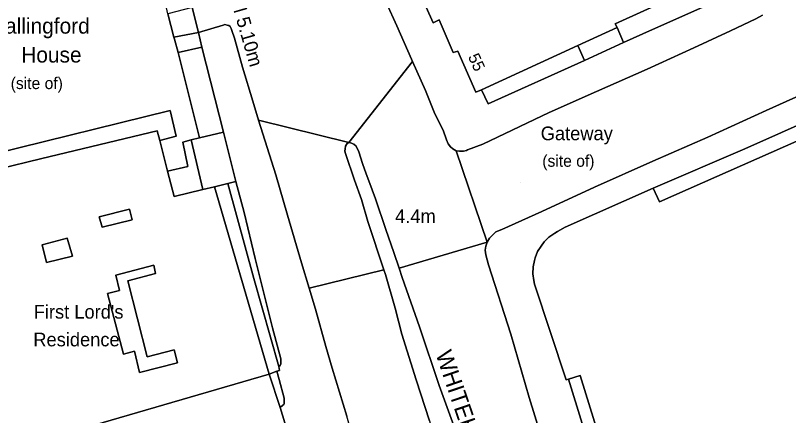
# Model space of a CAD drawing. Extents: x 529240 to 530363, y 179600 to 180767.
# Drawn here: x 530056.2 to 530155.2, y 180160.9 to 180212.1 of the extents above; entities that cross this region are included whole.
import ezdxf

# ---------------------------------------------------------------- set-up
doc = ezdxf.new("R2010")
doc.units = 0
for name, color, linetype in [('Building', 7, 'Continuous'), ('General surface', 7, 'Continuous'), ('Road Or Track', 7, 'Continuous'), ('Roadside', 7, 'Continuous'), ('Unclassified', 7, 'Continuous')]:
    doc.layers.add(name, color=color, linetype=linetype)

msp = doc.modelspace()

# ---------------------------------------------------------------- linework, layer by layer
at = {"layer": 'Building'}
for points in [[(530176.2, 180236.5), (530175.85, 180237.25), (530176.25, 180237.5), (530168, 180256.75), (530156.05, 180251.15), (530155.8, 180251.45), (530132.55, 180240.6), (530132.8, 180239.85), (530104.2, 180226.6), (530106.65, 180221.35), (530106.2, 180221.15), (530107.95, 180217.25), (530107.2, 180216.85), (530109.7, 180211.2), (530110.5, 180211.55), (530112.3, 180207.4), (530112.9, 180207.55), (530115.2, 180202.3), (530115.9, 180202.6)], [(530133.3, 180210.6), (530133.05, 180211.05), (530139.9, 180214.2), (530140.15, 180213.75), (530154.3, 180220.05)], [(530107.2, 180216.85), (530109.7, 180211.2), (530110.5, 180211.55), (530112.3, 180207.4), (530112.9, 180207.55), (530115.2, 180202.3), (530115.9, 180202.6), (530128.25, 180208.3), (530133.3, 180210.6), (530133.05, 180211.05), (530139.9, 180214.2)], [(530128.25, 180208.3), (530133.3, 180210.6)], [(530115.9, 180202.6), (530128.25, 180208.3)], [(530137.9, 180190), (530138.7, 180188.25), (530169.15, 180201.7), (530168.45, 180203.4)], [(530169.15, 180201.7), (530138.7, 180188.25), (530137.9, 180190), (530126.65, 180185), (530125.65, 180184.45), (530125.3, 180184.25), (530124.55, 180183.75), (530123.95, 180183.15), (530123.55, 180182.6), (530123.1, 180181.9), (530122.8, 180181.1), (530122.7, 180180.75), (530122.55, 180179.95), (530122.5, 180179.05), (530122.6, 180178.2), (530122.7, 180177.7), (530126.75, 180165.45), (530127.05, 180165.55), (530128.55, 180166), (530132.6, 180152.9)], [(530054.35, 180155.6), (530059.15, 180156.95), (530060.4, 180157.3), (530065.15, 180158.65), (530065.1, 180159.3), (530088.7, 180166.2), (530081.7, 180190.2), (530080.2, 180189.85), (530076.55, 180188.95), (530075.7, 180192.2), (530074.7, 180196.1), (530074.35, 180197.35), (530059.6, 180193.8), (530053.95, 180192.45)], [(530074.7, 180196.1), (530074.35, 180197.35), (530059.6, 180193.8), (530053.95, 180192.45)], [(530075.7, 180192.2), (530074.7, 180196.1)], [(530080.2, 180189.85), (530076.55, 180188.95), (530075.7, 180192.2)], [(530081.7, 180190.2), (530080.2, 180189.85)], [(530088.7, 180166.2), (530081.7, 180190.2)], [(530127.05, 180165.55), (530126.75, 180165.45), (530122.7, 180177.7), (530122.6, 180178.2), (530122.5, 180179.05), (530122.55, 180179.95), (530122.7, 180180.75), (530122.8, 180181.1), (530123.1, 180181.9), (530123.55, 180182.6), (530123.95, 180183.15), (530124.55, 180183.75), (530125.3, 180184.25), (530125.65, 180184.45), (530126.65, 180185), (530137.9, 180190)], [(530066.95, 180186.35), (530070.8, 180187.3), (530071.15, 180185.95), (530067.3, 180185), (530066.95, 180186.35)], [(530059.65, 180182.75), (530062.85, 180183.6), (530063.5, 180181.3), (530060.2, 180180.5), (530059.65, 180182.75)], [(530076.95, 180167.65), (530072.1, 180166.4), (530071.45, 180169.15), (530070.05, 180168.75), (530068, 180176.5), (530069.55, 180176.9), (530069.05, 180178.85), (530073.95, 180180.15), (530074.15, 180179.1), (530070.6, 180178.15), (530073.1, 180168.4), (530076.55, 180169.3), (530076.95, 180167.65)], [(530088.7, 180166.2), (530065.1, 180159.3), (530065.15, 180158.65), (530060.4, 180157.3)], [(530090.1, 180161.9), (530088.7, 180166.2)], [(530131.85, 180152.65), (530132.6, 180152.9), (530128.55, 180166), (530127.05, 180165.55)], [(530094.1, 180148.85), (530094.5, 180148.95), (530092.3, 180156.65), (530091.75, 180156.6), (530090.1, 180161.9)]]:
    msp.add_lwpolyline(points, dxfattribs=at)
for points in [[(530078.85, 180213.15), (530075.75, 180212.35), (530076.5, 180209.35), (530079.65, 180209.95)], [(530080.1, 180208.05), (530079.65, 180209.95), (530076.5, 180209.35), (530076.6, 180209.1), (530077.05, 180207.4)], [(530079.8, 180196.45), (530082.85, 180197.2), (530080.1, 180208.05), (530077.05, 180207.4)], [(530082.85, 180197.2), (530079.8, 180196.45), (530078.7, 180196.2), (530080.2, 180189.85), (530081.7, 180190.2), (530083.4, 180190.6), (530084.45, 180190.85)], [(530075.7, 180192.2), (530076.55, 180188.95), (530080.2, 180189.85), (530078.7, 180196.2), (530077.65, 180195.9), (530078.3, 180192.8)], [(530067.3, 180185), (530071.15, 180185.95), (530070.8, 180187.3), (530066.95, 180186.35)], [(530060.2, 180180.5), (530063.5, 180181.3), (530062.85, 180183.6), (530059.65, 180182.75)], [(530072.1, 180166.4), (530076.95, 180167.65), (530076.55, 180169.3), (530073.1, 180168.4), (530070.6, 180178.15), (530074.15, 180179.1), (530073.95, 180180.15), (530069.05, 180178.85), (530069.55, 180176.9), (530068, 180176.5), (530070.05, 180168.75), (530071.45, 180169.15)], [(530067.25, 180135.25), (530068.1, 180135.4), (530074.15, 180136.65), (530073.1, 180140.65), (530074, 180142.75), (530074.15, 180143.1), (530075.55, 180143.5), (530078.35, 180144.35), (530076.6, 180150.7), (530083.7, 180152.85), (530085.75, 180146.55), (530094.1, 180148.85), (530094.5, 180148.95), (530092.3, 180156.65), (530091.75, 180156.6), (530090.1, 180161.9), (530088.7, 180166.2), (530065.1, 180159.3), (530065.15, 180158.65), (530060.4, 180157.3), (530062.85, 180149.4), (530065.3, 180141.5)]]:
    msp.add_lwpolyline(points, close=True, dxfattribs=at)
at = {"layer": 'General surface'}
msp.add_lwpolyline([(530053.5, 180194.4), (530076.05, 180199.95), (530076.8, 180196.65), (530074.7, 180196.1), (530075.7, 180192.2), (530078.3, 180192.8), (530077.65, 180195.9), (530078.7, 180196.2), (530079.8, 180196.45), (530077.05, 180207.4), (530076.6, 180209.1), (530076.5, 180209.35), (530075.75, 180212.35), (530075.25, 180214.5), (530074, 180219.4), (530072.7, 180224.65), (530071.55, 180224.35), (530069.85, 180231.2), (530067.45, 180230.6), (530070.25, 180219.65), (530060.6, 180217.35), (530050.6, 180214.95)], dxfattribs=at)
for points in [[(530134.1, 180208.65), (530137.8, 180210.35), (530151.5, 180216.45), (530153.85, 180217.65), (530154.4, 180217.9), (530154.65, 180218.15), (530154.75, 180218.3), (530154.75, 180218.5), (530154.8, 180218.6), (530154.8, 180218.75), (530154.75, 180218.85), (530154.75, 180219.1), (530154.3, 180220.05), (530140.15, 180213.75), (530139.9, 180214.2), (530133.05, 180211.05), (530133.3, 180210.6)], [(530133.3, 180210.6), (530128.25, 180208.3), (530129.1, 180206.35), (530134.1, 180208.65)], [(530129.1, 180206.35), (530128.25, 180208.3), (530115.9, 180202.6), (530116.75, 180200.8)], [(530137.9, 180190), (530138.7, 180188.25), (530169.15, 180201.7), (530168.45, 180203.4), (530149.65, 180195.05)], [(530074.7, 180196.1), (530076.8, 180196.65), (530076.05, 180199.95), (530053.5, 180194.4), (530053.95, 180192.45), (530059.6, 180193.8), (530074.35, 180197.35)], [(530083.4, 180190.6), (530081.7, 180190.2), (530088.7, 180166.2), (530089.7, 180166.55), (530090.05, 180166.65), (530089.95, 180167.15), (530086.75, 180178.45)], [(530089.95, 180167.15), (530090.1, 180167.3), (530090.2, 180167.5), (530090.2, 180168.15), (530089.15, 180172.1), (530086.9, 180181), (530085.5, 180186.9), (530084.45, 180190.85), (530083.4, 180190.6), (530086.75, 180178.45)], [(530066.95, 180186.35), (530067.3, 180185), (530071.15, 180185.95), (530070.8, 180187.3)], [(530059.65, 180182.75), (530060.2, 180180.5), (530063.5, 180181.3), (530062.85, 180183.6)], [(530076.95, 180167.65), (530076.55, 180169.3), (530073.1, 180168.4), (530070.6, 180178.15), (530074.15, 180179.1), (530073.95, 180180.15), (530069.05, 180178.85), (530069.55, 180176.9), (530068, 180176.5), (530070.05, 180168.75), (530071.45, 180169.15), (530072.1, 180166.4)], [(530088.7, 180166.2), (530090.1, 180161.9), (530090.45, 180162.2), (530090.6, 180162.3), (530090.65, 180162.4), (530090.65, 180163.1), (530090, 180165.5), (530089.7, 180166.55)], [(530127.05, 180165.55), (530130.75, 180153.65), (530131.85, 180152.65), (530132.6, 180152.9), (530128.55, 180166)]]:
    msp.add_lwpolyline(points, close=True, dxfattribs=at)
at = {"layer": 'Road Or Track'}
for points in [[(530098.7, 180225.5), (530098.7, 180225), (530098.8, 180224.55), (530098.95, 180224.15), (530099.65, 180222.75), (530102.4, 180216.65), (530105.05, 180210.8), (530106.95, 180206.55), (530107.08, 180206.25)], [(530078.85, 180213.15), (530079.65, 180209.95), (530082.8, 180210.9), (530083.05, 180210.95), (530083.35, 180210.9), (530083.55, 180210.85), (530083.7, 180210.7), (530083.85, 180210.45), (530083.95, 180210.2), (530084.25, 180209.2), (530085.3, 180205.5), (530086.6, 180201.15), (530087.36, 180198.73), (530098.9, 180195.85), (530107.08, 180206.25), (530106.95, 180206.55), (530105.05, 180210.8), (530102.4, 180216.65)], [(530116.65, 180183.1), (530116.95, 180183.6), (530117.35, 180184.05), (530117.75, 180184.4), (530118.5, 180184.7), (530123.65, 180187), (530130.4, 180190.15), (530137.85, 180193.45), (530144.9, 180196.55), (530152.4, 180199.95), (530158.75, 180202.8), (530165.95, 180206.05), (530172.5, 180209.05), (530186.82, 180215.54)], [(530151.9, 180212.15), (530151.05, 180211.7), (530147.8, 180210.15), (530143.1, 180208), (530137.15, 180205.25), (530130.65, 180202.4), (530124.6, 180199.7), (530116.1, 180195.65), (530114.1, 180194.9), (530114, 180194.85), (530113.6, 180194.75), (530113.1, 180194.75), (530112.65, 180194.8), (530116.65, 180183.1), (530116.95, 180183.6), (530117.35, 180184.05), (530117.75, 180184.4), (530118.5, 180184.7), (530123.65, 180187), (530130.4, 180190.15), (530137.85, 180193.45), (530144.9, 180196.55), (530152.4, 180199.95), (530158.75, 180202.8)], [(530112.65, 180194.8), (530113.1, 180194.75), (530113.6, 180194.75), (530114, 180194.85), (530114.1, 180194.9), (530116.1, 180195.65), (530124.6, 180199.7), (530130.65, 180202.4), (530137.15, 180205.25), (530143.1, 180208), (530147.8, 180210.15), (530151.05, 180211.7), (530151.9, 180212.15)], [(530087.36, 180198.73), (530086.6, 180201.15), (530085.3, 180205.5), (530084.25, 180209.2), (530083.95, 180210.2), (530083.85, 180210.45), (530083.7, 180210.7), (530083.55, 180210.85), (530083.35, 180210.9), (530083.05, 180210.95), (530082.8, 180210.9), (530079.65, 180209.95)], [(530107.08, 180206.25), (530108.75, 180202.5), (530109.95, 180199.55), (530111, 180197.45), (530111.45, 180196.2), (530111.65, 180195.7), (530111.95, 180195.3), (530112.25, 180195.05), (530112.65, 180194.8)], [(530093.83, 180177.2), (530092.85, 180180.45), (530091.05, 180186.55), (530089.55, 180191.7), (530087.36, 180198.73)], [(530098.9, 180195.85), (530098.7, 180195.75), (530098.6, 180195.6), (530098.5, 180195.4), (530098.45, 180195.05), (530098.4, 180194.75), (530098.5, 180194.45), (530099.65, 180191.05), (530100.55, 180188.55), (530101.35, 180185.75), (530103.4, 180179.55)], [(530105.35, 180179.76), (530104.7, 180181.75), (530103.65, 180184.7), (530102.35, 180188.65), (530101.5, 180190.95), (530101.15, 180191.85), (530100.65, 180193.15), (530100.2, 180194.65), (530099.85, 180195.4), (530099.55, 180195.65), (530099.35, 180195.75), (530099.05, 180195.85), (530098.9, 180195.85)], [(530124.35, 180155.6), (530122, 180163.2), (530119.65, 180171.3), (530116.8, 180180.2), (530116.45, 180181.45), (530116.4, 180182.05), (530116.45, 180182.6), (530116.65, 180183.1), (530105.35, 180179.76), (530105.75, 180178.55), (530107.95, 180172.25), (530110.5, 180164.75), (530112.7, 180158.65)], [(530137.131, 180114), (530136.2, 180117.2), (530134.1, 180123.9), (530132.1, 180130.5), (530129.35, 180139.25), (530126.55, 180148.7), (530124.35, 180155.6), (530122, 180163.2), (530119.65, 180171.3), (530116.8, 180180.2), (530116.45, 180181.45), (530116.4, 180182.05), (530116.45, 180182.6), (530116.65, 180183.1)], [(530109.25, 180160.2), (530107.55, 180165.45), (530105.7, 180171.3), (530104.85, 180174.65), (530103.6, 180178.95), (530103.4, 180179.55), (530093.83, 180177.2), (530094.65, 180174.5), (530095.95, 180169.75), (530096.8, 180166.95), (530098.65, 180160.8)], [(530103.4, 180179.55), (530103.6, 180178.95), (530104.85, 180174.65), (530105.7, 180171.3), (530107.55, 180165.45), (530109.25, 180160.2), (530111.15, 180153.75), (530112.5, 180149.35), (530113.55, 180145.7), (530114.9, 180140.8), (530116.05, 180136.9), (530117.3, 180132.25), (530118.65, 180127.15), (530119.9, 180122.05), (530121.15, 180117.8), (530122.224, 180114)], [(530125.719, 180114), (530124.75, 180117.5), (530121.25, 180131.3), (530120.55, 180133.4), (530119.25, 180138.3), (530118.55, 180140.9), (530117.75, 180143.55), (530116.95, 180146.1), (530116, 180148.6), (530114.55, 180152.85), (530112.7, 180158.65), (530110.5, 180164.75), (530107.95, 180172.25), (530105.75, 180178.55), (530105.35, 180179.76)], [(530099.05, 180141.05), (530104.05, 180142.45), (530102.35, 180149), (530101.6, 180151.2), (530100.45, 180154.5), (530098.65, 180160.8), (530096.8, 180166.95), (530095.95, 180169.75), (530094.65, 180174.5), (530093.83, 180177.2)]]:
    msp.add_lwpolyline(points, dxfattribs=at)
for points in [[(530098.9, 180195.85), (530099.05, 180195.85), (530099.35, 180195.75), (530099.55, 180195.65), (530099.85, 180195.4), (530100.2, 180194.65), (530100.65, 180193.15), (530101.15, 180191.85), (530101.5, 180190.95), (530102.35, 180188.65), (530103.65, 180184.7), (530104.7, 180181.75), (530105.35, 180179.76), (530116.65, 180183.1), (530112.65, 180194.8), (530112.25, 180195.05), (530111.95, 180195.3), (530111.65, 180195.7), (530111.45, 180196.2), (530111, 180197.45), (530109.95, 180199.55), (530108.75, 180202.5), (530107.08, 180206.25)], [(530087.36, 180198.73), (530089.55, 180191.7), (530091.05, 180186.55), (530092.85, 180180.45), (530093.83, 180177.2), (530103.4, 180179.55), (530101.35, 180185.75), (530100.55, 180188.55), (530099.65, 180191.05), (530098.5, 180194.45), (530098.4, 180194.75), (530098.45, 180195.05), (530098.5, 180195.4), (530098.6, 180195.6), (530098.7, 180195.75), (530098.9, 180195.85)]]:
    msp.add_lwpolyline(points, close=True, dxfattribs=at)
at = {"layer": 'Roadside'}
for points in [[(530151.5, 180216.45), (530137.8, 180210.35), (530134.1, 180208.65), (530129.1, 180206.35), (530116.75, 180200.8), (530115.9, 180202.6), (530115.2, 180202.3), (530112.9, 180207.55), (530112.3, 180207.4), (530110.5, 180211.55), (530109.7, 180211.2), (530107.2, 180216.85)], [(530102.4, 180216.65), (530105.05, 180210.8), (530106.95, 180206.55), (530107.08, 180206.25), (530108.75, 180202.5), (530109.95, 180199.55), (530111, 180197.45), (530111.45, 180196.2), (530111.65, 180195.7), (530111.95, 180195.3), (530112.25, 180195.05), (530112.65, 180194.8), (530113.1, 180194.75), (530113.6, 180194.75), (530114, 180194.85), (530114.1, 180194.9), (530116.1, 180195.65), (530124.6, 180199.7), (530130.65, 180202.4), (530137.15, 180205.25), (530143.1, 180208), (530147.8, 180210.15), (530151.05, 180211.7), (530151.9, 180212.15)], [(530098.65, 180160.8), (530096.8, 180166.95), (530095.95, 180169.75), (530094.65, 180174.5), (530093.83, 180177.2), (530092.85, 180180.45), (530091.05, 180186.55), (530089.55, 180191.7), (530087.36, 180198.73), (530086.6, 180201.15), (530085.3, 180205.5), (530084.25, 180209.2), (530083.95, 180210.2), (530083.85, 180210.45), (530083.7, 180210.7), (530083.55, 180210.85), (530083.35, 180210.9), (530083.05, 180210.95), (530082.8, 180210.9), (530079.65, 180209.95), (530080.1, 180208.05), (530082.85, 180197.2), (530084.45, 180190.85), (530085.5, 180186.9), (530086.9, 180181), (530089.15, 180172.1), (530090.2, 180168.15), (530090.2, 180167.5), (530090.1, 180167.3), (530089.95, 180167.15), (530090.05, 180166.65), (530089.7, 180166.55), (530090, 180165.5), (530090.65, 180163.1), (530090.65, 180162.4), (530090.6, 180162.3), (530090.45, 180162.2), (530090.1, 180161.9), (530091.75, 180156.6)], [(530130.75, 180153.65), (530127.05, 180165.55), (530126.75, 180165.45), (530122.7, 180177.7), (530122.6, 180178.2), (530122.5, 180179.05), (530122.55, 180179.95), (530122.7, 180180.75), (530122.8, 180181.1), (530123.1, 180181.9), (530123.55, 180182.6), (530123.95, 180183.15), (530124.55, 180183.75), (530125.3, 180184.25), (530125.65, 180184.45), (530126.65, 180185), (530137.9, 180190), (530149.65, 180195.05), (530168.45, 180203.4)], [(530158.75, 180202.8), (530152.4, 180199.95), (530144.9, 180196.55), (530137.85, 180193.45), (530130.4, 180190.15), (530123.65, 180187), (530118.5, 180184.7), (530117.75, 180184.4), (530117.35, 180184.05), (530116.95, 180183.6), (530116.65, 180183.1), (530116.45, 180182.6), (530116.4, 180182.05), (530116.45, 180181.45), (530116.8, 180180.2), (530119.65, 180171.3), (530122, 180163.2), (530124.35, 180155.6)], [(530112.7, 180158.65), (530110.5, 180164.75), (530107.95, 180172.25), (530105.75, 180178.55), (530105.35, 180179.76), (530104.7, 180181.75), (530103.65, 180184.7), (530102.35, 180188.65), (530101.5, 180190.95), (530101.15, 180191.85), (530100.65, 180193.15), (530100.2, 180194.65), (530099.85, 180195.4), (530099.55, 180195.65), (530099.35, 180195.75), (530099.05, 180195.85), (530098.9, 180195.85), (530098.7, 180195.75), (530098.6, 180195.6), (530098.5, 180195.4), (530098.45, 180195.05), (530098.4, 180194.75), (530098.5, 180194.45), (530099.65, 180191.05), (530100.55, 180188.55), (530101.35, 180185.75), (530103.4, 180179.55), (530103.6, 180178.95), (530104.85, 180174.65), (530105.7, 180171.3), (530107.55, 180165.45), (530109.25, 180160.2)]]:
    msp.add_lwpolyline(points, dxfattribs=at)
at = {"layer": 'Unclassified'}
for p, q in [((530120.9, 180190.7), (530120.9, 180190.7)), ((530102.85, 180184.3), (530102.85, 180184.3))]:
    msp.add_line(p, q, dxfattribs=at)
for points in [[(530134.1, 180208.65), (530137.8, 180210.35), (530151.5, 180216.45), (530153.85, 180217.65), (530154.4, 180217.9), (530154.65, 180218.15), (530154.75, 180218.3), (530154.75, 180218.5), (530154.8, 180218.6), (530154.8, 180218.75), (530154.75, 180218.85), (530154.75, 180219.1)], [(530078.85, 180213.15), (530079.65, 180209.95)], [(530076.5, 180209.35), (530075.75, 180212.35)], [(530079.65, 180209.95), (530076.5, 180209.35)], [(530079.65, 180209.95), (530080.1, 180208.05)], [(530133.3, 180210.6), (530134.1, 180208.65)], [(530077.05, 180207.4), (530076.6, 180209.1), (530076.5, 180209.35)], [(530077.05, 180207.4), (530080.1, 180208.05)], [(530080.1, 180208.05), (530082.85, 180197.2)], [(530129.1, 180206.35), (530128.25, 180208.3)], [(530129.1, 180206.35), (530134.1, 180208.65)], [(530079.8, 180196.45), (530077.05, 180207.4)], [(530098.9, 180195.85), (530107.08, 180206.25)], [(530115.9, 180202.6), (530116.75, 180200.8), (530129.1, 180206.35)], [(530168.45, 180203.4), (530149.65, 180195.05), (530137.9, 180190)], [(530074.7, 180196.1), (530076.8, 180196.65), (530076.05, 180199.95), (530053.5, 180194.4), (530053.95, 180192.45)], [(530098.9, 180195.85), (530087.36, 180198.73)], [(530079.8, 180196.45), (530082.85, 180197.2)], [(530082.85, 180197.2), (530084.45, 180190.85)], [(530075.7, 180192.2), (530078.3, 180192.8), (530077.65, 180195.9), (530078.7, 180196.2)], [(530078.7, 180196.2), (530079.8, 180196.45)], [(530078.7, 180196.2), (530080.2, 180189.85)], [(530116.65, 180183.1), (530112.65, 180194.8)], [(530083.4, 180190.6), (530081.7, 180190.2)], [(530084.45, 180190.85), (530083.4, 180190.6)], [(530089.95, 180167.15), (530086.75, 180178.45), (530083.4, 180190.6)], [(530089.95, 180167.15), (530090.1, 180167.3), (530090.2, 180167.5), (530090.2, 180168.15), (530089.15, 180172.1), (530086.9, 180181), (530085.5, 180186.9), (530084.45, 180190.85)], [(530116.65, 180183.1), (530105.35, 180179.76)], [(530093.83, 180177.2), (530103.4, 180179.55)], [(530089.7, 180166.55), (530088.7, 180166.2)], [(530089.7, 180166.55), (530090.05, 180166.65), (530089.95, 180167.15)], [(530090.1, 180161.9), (530090.45, 180162.2), (530090.6, 180162.3), (530090.65, 180162.4), (530090.65, 180163.1), (530090, 180165.5), (530089.7, 180166.55)], [(530127.05, 180165.55), (530130.75, 180153.65), (530131.85, 180152.65)]]:
    msp.add_lwpolyline(points, dxfattribs=at)

# ---------------------------------------------------------------- texts
at = {"layer": 'Road Or Track'}
msp.add_text('WHITEHALL', height=2.125, rotation=288.8, dxfattribs=at).set_placement((530110, 180168.8))
at = {"layer": 'Unclassified'}
for s, height, rotation, p in [('BM 5.10m', 1.75, 286.2, (530083.3, 180215.65)), ('55', 1.5, 294.5, (530114.15, 180206.85))]:
    msp.add_text(s, height=height, rotation=rotation, dxfattribs=at).set_placement(p)
for s, height, p in [('Wallingford', 2, (530052.35, 180209.8)), ('House', 2, (530056.95, 180206.1)), ('(site of)', 1.5, (530055.6, 180202.7)), ('Gateway', 1.75, (530123.5, 180196.15)), ('(site of)', 1.5, (530123.7, 180192.75)), ('4.4m', 1.75, (530104.85, 180185.55)), ("First Lord's", 1.75, (530058.55, 180173.3)), ('Residence', 1.75, (530058.5, 180169.75))]:
    msp.add_text(s, height=height, dxfattribs=at).set_placement(p)

doc.saveas('drawing.dxf')
